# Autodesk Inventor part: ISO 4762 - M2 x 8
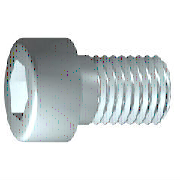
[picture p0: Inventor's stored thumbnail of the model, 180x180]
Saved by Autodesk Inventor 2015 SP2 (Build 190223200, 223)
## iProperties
IsCustomPart: 0
Created: 2012-02
Part Number: ISO 4762 - M2 x 8
Material: Edelstahl, 440C
Description: Innensechskantschraube
Document SubType Name: Modeling
Standard: ISO 4762
Designer: rYan
Standard Revision: 1998
Standards Organization: DIN
Language: de-DE
Size Designation: M2 x 8
Categories: <MemberInstance><Categories><Category DisplayName="Verbindungselemente" InternalName="e4da775c-781d-43d5-af7c-5136215cf5a6" Mnemonic="FSTN"><Category DisplayNam
Density: 7.75 g/cm^3
Appearance: Halbpoliert
Author: rYan
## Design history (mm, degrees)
sketch "Skizze1"
  geometry: L1 (-0.5, 0)-(8, 0); L2 (8, 0)-(8, 1); L3 (8, 1)-(1, 1); L4 (1, 1)-(0.755, 1); L5 (0.755, 1)-(0, 1); L6 (0, 1)-(0, 1.9); L7 (0, 1.9)-(-2, 1.9); L8 (-2, 1.9)-(-2, 0.866); L9 (-2, 0.866)-(-1, 0.866); L10 (-1, 0.866)-(-0.5, 0); L11 (-4, 0)-(10, 0) reference; L12 (0, -0.38)-(0, 2.28) reference; L13 (1, 1)-(0, 1)
  constraints: 22 end point, 6 parallel, 2 collinear, 2 perpendicular, 1 horizontal, 1 point on line
  dimensions: "d1" = 7 distance from line of L3.end L2 (= GEL); "d2" = 0.24548 distance of L4.end L3.end (computed from GAL); "d3" = 2 distance between parallel lines of L8 L6 (= KOH); "d4" = 1 distance of L8.end L9.end (= INTI); "d5" = 60 deg angle of L10 L1; "d6" = 2 diameter of L3 L1 (= GD); "d7" = 2 diameter of L5 L1 (= BDM); "d8" = 1.73205 diameter of L9 L1 (= 1.1547 x SW); "d9" = 3.8 diameter of L7 L1 (= KOD); "d26" = 8 distance between parallel lines of L12 L2 (= NLG)
revolve "Körper" sketch "Skizze1" stored, may be unused: angle "d10" = 90 deg
sketch "Skizze2"
  geometry: L1 (0, -2.66)-(0, 2.66) reference; L2 (-2.66, 0)-(2.66, 0) reference; L3 (0.866, 0)-(0.433, -0.75); L4 (0.433, -0.75)-(-0.433, -0.75); L5 (-0.433, -0.75)-(-0.866, 0); L6 (-0.866, 0)-(-0.433, 0.75); L7 (-0.433, 0.75)-(0.433, 0.75); L8 (0.433, 0.75)-(0.866, 0); 2 further points
  constraints: 12 end point, 1 coincident, 1 horizontal alignment, 1 point on line, 12 other
extrude "Loch" join sketch "Skizze2" stored distance "d11" = 10; taper "d12" = 0 deg
workplane "Work Plane1"
fillet "Fillet2" dims "d30" = 0.1 (= R)
body "Solid1"
fillet "Rundung1" dims "d17" = 0.2 (= RR)
feature "Gewinde" dims "d13" = 7 (= GEL), "d14" = 0
chamfer "Fase1" distance "d15" = 0.24538 (= -0.5 x SPD + 0.5 x GD); stored, may be unused: second distance "d16" = 0.24538 (= GUL), angle "d27" = 45 deg
other parameters: "GD" = 2 [user parameter; used in 2 equation terms], "NLG" = 8 [user parameter; used in 1 equation term], "GEL" = 7 [user parameter; used in 2 equation terms], "KOD" = 3.8 [user parameter; used in 1 equation term], "KOH" = 2 [user parameter; used in 1 equation term], "INTI" = 1 [user parameter; used in 1 equation term], "GAL" = 0.24538 (= 0.61345 x PTC) [user parameter; used in 1 equation term], "GUL" = 0.24538 (= 0.61345 x PTC) [user parameter; used in 1 equation term], "BDM" = 2 (= NND) [user parameter; used in 1 equation term], "SW" = 1.5 [user parameter; used in 2 equation terms], "RR" = 0.2 [user parameter; used in 1 equation term], "SPD" = 1.50924 (= NND - 1.2269 x PTC) [user parameter; used in 1 equation term], "d19" = 0, "d28" = 0, "d29" = 0, "R" = 0.1 [user parameter; used in 1 equation term], "TOA" = 30 deg [user parameter], "GD1" = 1.50924 (= THREADDIA - 1.2269 x PTC) [user parameter], "THREADDIA" = 2 [user parameter; used in 1 equation term], "FAWI" = 45 deg [user parameter], "TPU" = 25 (computed from PTC) [user parameter], "PTC" = 0.4 [user parameter; used in 5 equation terms], "NND" = 2 [user parameter; used in 2 equation terms], "E0" = 1.7325 (= 1.155 x SW) [user parameter]
